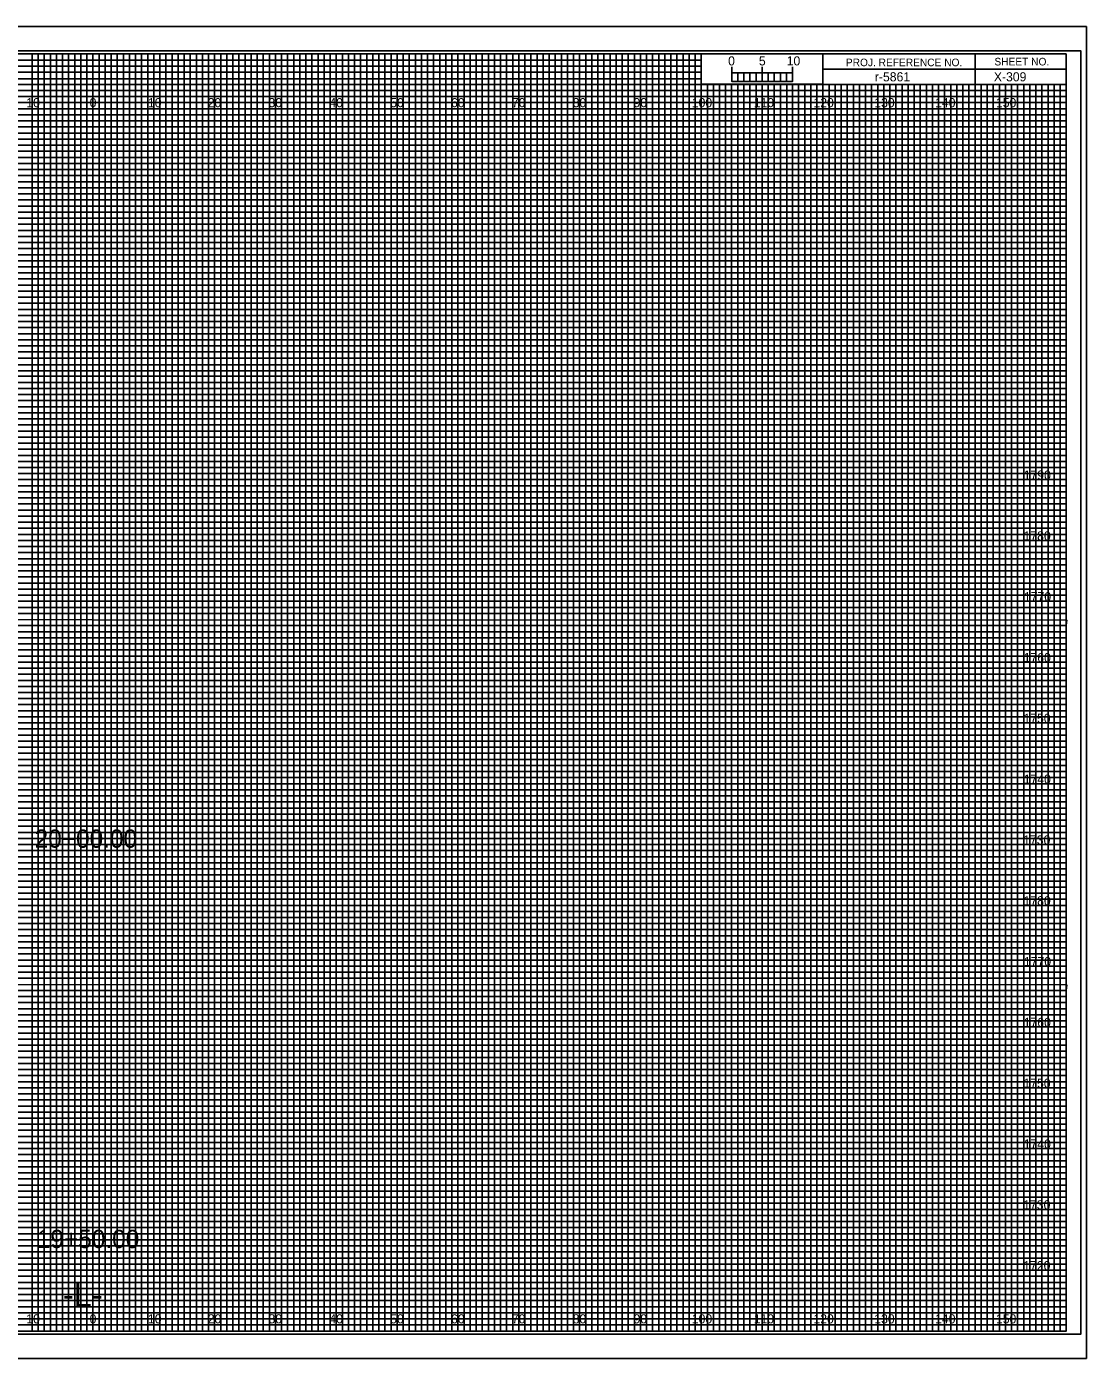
# Model space of a CAD drawing. Extents: x -15 to 323, y -5 to 6170.
# Drawn here: x 149.1 to 323.3, y 1095.5 to 1314.5 of the extents above; entities that cross this region are included whole.
import ezdxf

# ---------------------------------------------------------------- set-up
doc = ezdxf.new("R2010")
doc.units = 0
for name, color, linetype in [('Prop XS Alignment Label', 7, 'Continuous'), ('Prop XS Bar Scale Labels', 7, 'Continuous'), ('Prop XS DDE', 7, 'Continuous'), ('Prop XS DDE Earthwork Shape', 7, 'Continuous'), ('Prop XS DDE Slope Text', 7, 'Continuous'), ('Prop XS DDE Text', 7, 'Continuous'), ('Prop XS Earthwork Shape', 7, 'Continuous'), ('Prop XS Noise Wall', 7, 'Continuous'), ('Prop XS Project Number', 7, 'Continuous'), ('Prop XS Retaining Wall', 7, 'Continuous'), ('Prop XS Station Labels', 7, 'Continuous'), ('Prop XS Temporary Shoring', 7, 'Continuous'), ('Scratch_Level_3', 7, 'Continuous'), ('Scratch_Level_7', 7, 'Continuous'), ('Scratch_Level_8', 7, 'Continuous'), ('Sheet Cross Section Grid Minor 1 CELL', 7, 'Continuous')]:
    doc.layers.add(name, color=color, linetype=linetype)

msp = doc.modelspace()

# ---------------------------------------------------------------- linework, layer by layer
at = {"layer": 'Prop XS Alignment Label'}
for p, q in [((265, 1305.49), (265, 1307.9)), ((265, 1306.9), (265, 1307.9)), ((270, 1305.49), (270, 1307.9)), ((275, 1305.49), (275, 1307.9)), ((275, 1306.9), (275, 1307.9))]:
    msp.add_line(p, q, dxfattribs=at)
for points in [[(275, 1306.9), (265, 1306.9), (265, 1305.49), (275, 1305.49)], [(265, 1306.9), (266, 1306.9), (266, 1305.49), (265, 1305.49)], [(267, 1306.9), (268, 1306.9), (268, 1305.49), (267, 1305.49)], [(269, 1306.9), (270, 1306.9), (270, 1305.49), (269, 1305.49)], [(271, 1306.9), (272, 1306.9), (272, 1305.49), (271, 1305.49)], [(273, 1306.9), (274, 1306.9), (274, 1305.49), (273, 1305.49)]]:
    msp.add_lwpolyline(points, close=True, dxfattribs=at)
at = {"layer": 'Prop XS DDE'}
msp.add_lwpolyline([(-13.4, 1095.5), (323.3, 1095.5), (323.3, 1314.5), (-13.4, 1314.5)], close=True, dxfattribs=at)
at = {"layer": 'Prop XS DDE Slope Text'}
msp.add_lwpolyline([(-10.8, 1099.5), (322.4, 1099.5), (322.4, 1310.5), (-10.8, 1310.5)], close=True, dxfattribs=at)
at = {"layer": 'Prop XS DDE Text'}
for p, q in [((150, 1100), (150, 1310)), ((160, 1100), (160, 1310)), ((170, 1100), (170, 1310)), ((180, 1100), (180, 1310)), ((190, 1100), (190, 1310)), ((200, 1100), (200, 1310)), ((210, 1100), (210, 1310)), ((220, 1100), (220, 1310)), ((230, 1100), (230, 1310)), ((240, 1100), (240, 1310)), ((250, 1100), (250, 1310)), ((260, 1100), (260, 1304.69)), ((270, 1100), (270, 1304.69)), ((280, 1100), (280, 1304.69)), ((290, 1100), (290, 1304.69)), ((300, 1100), (300, 1304.69)), ((310, 1100), (310, 1304.69)), ((0, 1300), (320, 1300)), ((0, 1290), (320, 1290)), ((0, 1280), (320, 1280)), ((0, 1270), (320, 1270)), ((0, 1260), (320, 1260)), ((0, 1250), (320, 1250)), ((0, 1240), (320, 1240)), ((0, 1230), (320, 1230)), ((0, 1220), (320, 1220)), ((0, 1210), (320, 1210)), ((0, 1200), (320, 1200)), ((0, 1190), (320, 1190)), ((0, 1180), (320, 1180)), ((0, 1170), (320, 1170)), ((0, 1160), (320, 1160)), ((0, 1150), (320, 1150)), ((0, 1140), (320, 1140)), ((0, 1130), (320, 1130)), ((0, 1120), (320, 1120)), ((0, 1110), (320, 1110))]:
    msp.add_line(p, q, dxfattribs=at)
at = {"layer": 'Prop XS Earthwork Shape'}
for p, q in [((150, 1310), (140, 1310)), ((150, 1100), (150, 1310)), ((170, 1310), (160, 1310)), ((160, 1310), (160, 1100)), ((170, 1100), (170, 1310)), ((190, 1310), (180, 1310)), ((180, 1310), (180, 1100)), ((190, 1100), (190, 1310)), ((210, 1310), (200, 1310)), ((200, 1310), (200, 1100)), ((210, 1100), (210, 1310)), ((230, 1310), (220, 1310)), ((220, 1310), (220, 1100)), ((230, 1100), (230, 1310)), ((250, 1310), (240, 1310)), ((240, 1310), (240, 1100)), ((250, 1100), (250, 1310)), ((260, 1310), (260, 1100)), ((270, 1100), (270, 1305)), ((290, 1305), (280, 1305)), ((280, 1305), (280, 1100)), ((290, 1100), (290, 1305)), ((310, 1305), (300, 1305)), ((300, 1305), (300, 1100)), ((310, 1100), (310, 1305)), ((160, 1100), (150, 1100)), ((180, 1100), (170, 1100)), ((200, 1100), (190, 1100)), ((220, 1100), (210, 1100)), ((240, 1100), (230, 1100)), ((260, 1100), (250, 1100)), ((280, 1100), (270, 1100)), ((300, 1100), (290, 1100)), ((320, 1100), (310, 1100)), ((320, 1100), (320, 1100))]:
    msp.add_line(p, q, dxfattribs=at)
for points in [[(0, 1300), (320, 1300), (320, 1290), (0, 1290)], [(0, 1280), (320, 1280), (320, 1270), (0, 1270)], [(0, 1260), (320, 1260), (320, 1250), (0, 1250)], [(0, 1240), (320, 1240), (320, 1230), (0, 1230)], [(0, 1220), (320, 1220), (320, 1210), (0, 1210)], [(0, 1200), (320, 1200), (320, 1190), (0, 1190)], [(0, 1180), (320, 1180), (320, 1170), (0, 1170)], [(0, 1160), (320, 1160), (320, 1150), (0, 1150)], [(0, 1140), (320, 1140), (320, 1130), (0, 1130)], [(0, 1120), (320, 1120), (320, 1110), (0, 1110)]]:
    msp.add_lwpolyline(points, dxfattribs=at)
at = {"layer": 'Prop XS Noise Wall'}
for p, q in [((305, 1310), (305, 1305)), ((305, 1305), (305, 1310)), ((280, 1307.5), (280, 1305)), ((320, 1307.49), (280, 1307.49)), ((280, 1305), (320, 1305))]:
    msp.add_line(p, q, dxfattribs=at)
for points in [[(320, 1310), (0, 1310), (0, 1100), (320, 1100)], [(280, 1310), (260, 1310), (260, 1305.03), (280, 1305.03)], [(320, 1310), (280, 1310), (280, 1305), (320, 1305)]]:
    msp.add_lwpolyline(points, close=True, dxfattribs=at)
at = {"layer": 'Prop XS Retaining Wall'}
for p, q in [((267, 1305), (266.01, 1305)), ((266.01, 1305), (266.01, 1100)), ((267, 1100), (267, 1305)), ((269, 1305), (268, 1305)), ((268, 1305), (268, 1100)), ((269, 1100), (269, 1305)), ((266.01, 1100), (265, 1100)), ((268, 1100), (267, 1100))]:
    msp.add_line(p, q, dxfattribs=at)
for points in [[(150, 1100), (151, 1100), (151, 1310), (152, 1310), (152, 1100)], [(152, 1100), (153, 1100), (153, 1310), (154, 1310), (154, 1100)], [(155, 1100), (156, 1100), (156, 1310), (157, 1310), (157, 1100)], [(157, 1100), (158, 1100), (158, 1310), (159, 1310), (159, 1100)], [(160, 1100), (161, 1100), (161, 1310), (162, 1310), (162, 1100)], [(162, 1100), (163, 1100), (163, 1310), (164, 1310), (164, 1100)], [(165, 1100), (166, 1100), (166, 1310), (167, 1310), (167, 1100)], [(167, 1100), (168, 1100), (168, 1310), (169, 1310), (169, 1100)], [(170, 1100), (171, 1100), (171, 1310), (172, 1310), (172, 1100)], [(172, 1100), (173, 1100), (173, 1310), (174, 1310), (174, 1100)], [(175, 1100), (176, 1100), (176, 1310), (177, 1310), (177, 1100)], [(177, 1100), (178, 1100), (178, 1310), (179, 1310), (179, 1100)], [(180, 1100), (181, 1100), (181, 1310), (182, 1310), (182, 1100)], [(182, 1100), (183, 1100), (183, 1310), (184, 1310), (184, 1100)], [(185, 1100), (186, 1100), (186, 1310), (187, 1310), (187, 1100)], [(187, 1100), (188, 1100), (188, 1310), (189, 1310), (189, 1100)], [(190, 1100), (191, 1100), (191, 1310), (192, 1310), (192, 1100)], [(192, 1100), (193, 1100), (193, 1310), (194, 1310), (194, 1100)], [(195, 1100), (196, 1100), (196, 1310), (197, 1310), (197, 1100)], [(197, 1100), (198, 1100), (198, 1310), (199, 1310), (199, 1100)], [(200, 1100), (201, 1100), (201, 1310), (202, 1310), (202, 1100)], [(202, 1100), (203, 1100), (203, 1310), (204, 1310), (204, 1100)], [(205, 1100), (206, 1100), (206, 1310), (207, 1310), (207, 1100)], [(207, 1100), (208, 1100), (208, 1310), (209, 1310), (209, 1100)], [(210, 1100), (211, 1100), (211, 1310), (212, 1310), (212, 1100)], [(212, 1100), (213, 1100), (213, 1310), (214, 1310), (214, 1100)], [(215, 1100), (216, 1100), (216, 1310), (217, 1310), (217, 1100)], [(217, 1100), (218, 1100), (218, 1310), (219, 1310), (219, 1100)], [(220, 1100), (221, 1100), (221, 1310), (222, 1310), (222, 1100)], [(222, 1100), (223, 1100), (223, 1310), (224, 1310), (224, 1100)], [(225, 1100), (226, 1100), (226, 1310), (227, 1310), (227, 1100)], [(227, 1100), (228, 1100), (228, 1310), (229, 1310), (229, 1100)], [(230, 1100), (231, 1100), (231, 1310), (232, 1310), (232, 1100)], [(232, 1100), (233, 1100), (233, 1310), (234, 1310), (234, 1100)], [(235, 1100), (236, 1100), (236, 1310), (237, 1310), (237, 1100)], [(237, 1100), (238, 1100), (238, 1310), (239, 1310), (239, 1100)], [(240, 1100), (241, 1100), (241, 1310), (242, 1310), (242, 1100)], [(242, 1100), (243, 1100), (243, 1310), (244, 1310), (244, 1100)], [(245, 1100), (246, 1100), (246, 1310), (247, 1310), (247, 1100)], [(247, 1100), (248, 1100), (248, 1310), (249, 1310), (249, 1100)], [(250, 1100), (251, 1100), (251, 1310), (252, 1310), (252, 1100)], [(252, 1100), (253, 1100), (253, 1310), (254, 1310), (254, 1100)], [(255, 1100), (256, 1100), (256, 1310), (257, 1310), (257, 1100)], [(257, 1100), (258, 1100), (258, 1310), (259, 1310), (259, 1100)], [(260, 1100), (261, 1100), (261, 1305), (262.02, 1305), (262.02, 1100)], [(262, 1100), (263, 1100), (263, 1305), (263.99, 1305), (263.99, 1100)], [(270, 1100), (270.98, 1100), (270.98, 1305), (272, 1305), (272, 1100)], [(272, 1100), (273, 1100), (273, 1305), (274.05, 1305), (274.05, 1100)], [(275, 1100), (276, 1100), (276, 1305), (277, 1305), (277, 1100)], [(277, 1100), (278, 1100), (278, 1305), (279, 1305), (279, 1100)], [(280, 1100), (281, 1100), (281, 1305), (282, 1305), (282, 1100)], [(282, 1100), (283, 1100), (283, 1305), (284, 1305), (284, 1100)], [(285, 1100), (286, 1100), (286, 1305), (287, 1305), (287, 1100)], [(287, 1100), (288, 1100), (288, 1305), (289, 1305), (289, 1100)], [(290, 1100), (291, 1100), (291, 1305), (292, 1305), (292, 1100)], [(292, 1100), (293, 1100), (293, 1305), (294, 1305), (294, 1100)], [(295, 1100), (296, 1100), (296, 1305), (297, 1305), (297, 1100)], [(297, 1100), (298, 1100), (298, 1305), (299, 1305), (299, 1100)], [(300, 1100), (301, 1100), (301, 1305), (302, 1305), (302, 1100)], [(302, 1100), (303, 1100), (303, 1305), (304, 1305), (304, 1100)], [(305, 1100), (306, 1100), (306, 1305), (307, 1305), (307, 1100)], [(307, 1100), (308, 1100), (308, 1305), (309, 1305), (309, 1100)], [(310, 1100), (311, 1100), (311, 1305), (312, 1305), (312, 1100)], [(312, 1100), (313, 1100), (313, 1305), (314, 1305), (314, 1100)], [(315, 1100), (316, 1100), (316, 1305), (317, 1305), (317, 1100)], [(317, 1100), (318, 1100), (318, 1305), (319, 1305), (319, 1100)]]:
    msp.add_lwpolyline(points, dxfattribs=at)
at = {"layer": 'Prop XS Station Labels'}
for points in [[(145, 1100), (155, 1100), (155, 1310), (165, 1310), (165, 1100), (175, 1100), (175, 1310), (185, 1310), (185, 1100), (195, 1100), (195, 1310), (205, 1310), (205, 1100), (215, 1100), (215, 1310), (225, 1310), (225, 1100), (235, 1100), (235, 1310), (245, 1310), (245, 1100), (255, 1100), (255, 1310), (259.93, 1310), (260, 1310), (260, 1305), (264.99, 1305), (264.99, 1100), (275, 1100), (275, 1305), (285, 1305), (285, 1100), (295, 1100), (295, 1305), (305, 1305), (305, 1100), (315, 1100), (315, 1305)], [(0, 1305), (275, 1305)], [(0, 1285), (320, 1285), (320, 1295), (0, 1295)], [(0, 1265), (320, 1265), (320, 1275), (0, 1275)], [(0, 1245), (320, 1245), (320, 1255), (0, 1255)], [(0, 1225), (320, 1225), (320, 1235), (0, 1235)], [(0, 1205), (320, 1205), (320, 1215), (0, 1215)], [(0, 1185), (320, 1185), (320, 1195), (0, 1195)], [(0, 1165), (320, 1165), (320, 1175), (0, 1175)], [(0, 1145), (320, 1145), (320, 1155), (0, 1155)], [(0, 1125), (320, 1125), (320, 1135), (0, 1135)], [(0, 1105), (320, 1105), (320, 1115), (0, 1115)]]:
    msp.add_lwpolyline(points, dxfattribs=at)
at = {"layer": 'Scratch_Level_7'}
for p, q in [((323.3, 1314.5), (-13.4, 1314.5)), ((-13.4, 1095.5), (323.3, 1095.5))]:
    msp.add_line(p, q, dxfattribs=at)
at = {"layer": 'Sheet Cross Section Grid Minor 1 CELL'}
for p, q in [((0, 1309), (260, 1309)), ((260, 1307.98), (0, 1307.98)), ((260, 1309), (260, 1307.98)), ((0, 1307), (260, 1307)), ((260, 1305.89), (0, 1305.89)), ((260, 1307), (260, 1305.89)), ((0, 1304), (320, 1304))]:
    msp.add_line(p, q, dxfattribs=at)
for points in [[(0, 1303), (270, 1303), (320, 1303), (320, 1302), (0, 1302)], [(0, 1301), (320, 1301), (320, 1299), (0, 1299)], [(0, 1298), (320, 1298), (320, 1297), (0, 1296.98)], [(0, 1296), (320, 1296), (320, 1294), (0, 1294)], [(0, 1293), (320, 1293), (320, 1292), (0, 1292)], [(0, 1291), (320, 1291), (320, 1289), (0, 1289)], [(0, 1288), (320, 1288), (320, 1287), (0, 1287)], [(0, 1286), (320, 1286), (320, 1284), (0, 1284)], [(0, 1283), (320, 1283), (320, 1282), (0, 1282)], [(0, 1281), (320, 1281), (320, 1279), (0, 1279)], [(0, 1278), (320, 1278), (320, 1277), (0, 1277)], [(0, 1276), (320, 1276), (320, 1273.95), (320, 1273), (320, 1272), (0, 1272)], [(0, 1274), (320, 1274), (320, 1273), (0, 1273)], [(0, 1271), (320, 1271), (320, 1269), (0, 1269.03)], [(0, 1269.03), (320, 1269), (320, 1268), (0, 1268)], [(0, 1267), (320, 1267), (320, 1266), (0, 1266)], [(0, 1264), (320, 1264), (320, 1263), (0, 1263)], [(0, 1262), (320, 1262), (320, 1261), (0, 1261)], [(-0.07, 1258.89), (320, 1258.89), (320, 1257.88), (-0.07, 1257.88)], [(0, 1257), (320, 1257), (320, 1256), (0, 1256)], [(0, 1254), (320, 1254), (320, 1253), (0, 1253)], [(0, 1252), (320, 1252), (320, 1251), (0, 1251)], [(0, 1249), (320, 1249), (320, 1248), (0, 1248)], [(0, 1247), (320, 1247), (320, 1246), (0, 1246)], [(0, 1244), (320, 1244), (320, 1243), (0, 1243)], [(0, 1242), (320, 1242), (320, 1241), (0, 1241)], [(0, 1239), (320, 1239), (319.99, 1237.98), (0, 1238)], [(0, 1237), (320, 1237), (320, 1236), (0, 1236)], [(0, 1234), (320, 1234), (320, 1233), (0, 1233)], [(0, 1232), (320, 1232), (320, 1231), (0, 1231)], [(0, 1229), (320, 1229), (320, 1228), (0, 1228)], [(0, 1227), (320, 1227), (320, 1226), (0, 1226)], [(0, 1224), (320, 1224), (320, 1223), (0, 1223)], [(0, 1222), (320, 1222), (320, 1221), (0, 1221)], [(0, 1219), (320, 1219), (320, 1218), (0, 1218)], [(0, 1216.99), (320.07, 1216.91), (320, 1216), (0, 1216)], [(0, 1214), (320, 1214), (320, 1213), (0, 1213)], [(0, 1212), (320, 1212), (320, 1211), (0, 1211)], [(0, 1209), (320, 1209), (320, 1208), (0, 1208)], [(0, 1207), (320, 1207), (320, 1206), (0, 1206)], [(0, 1204), (320, 1204), (320, 1203), (0, 1203)], [(0, 1202), (320, 1202), (320, 1201), (0, 1201)], [(0, 1199), (320, 1199), (320, 1198), (0, 1198)], [(0, 1197), (320, 1197), (320, 1196), (0, 1196)], [(0, 1194), (320, 1194), (320, 1193), (0, 1193)], [(0, 1192), (320, 1192), (320, 1191), (0, 1191)], [(0, 1189), (320, 1189), (320, 1188), (0, 1188)], [(0, 1187), (320, 1187), (320, 1186), (0, 1186)], [(0, 1184), (320, 1184), (320, 1183), (0, 1183)], [(0, 1182), (320, 1182), (320, 1181), (0, 1181)], [(0, 1179), (320, 1179), (319.99, 1177.98), (0, 1178)], [(0, 1177), (320, 1177), (320, 1176), (0, 1176)], [(0, 1174), (320, 1174), (320, 1173), (0, 1173)], [(0, 1172), (320, 1172), (320, 1171), (0, 1171)], [(0, 1169), (320, 1169), (320, 1168), (0, 1168)], [(0, 1167), (320, 1167), (320, 1166), (0, 1166)], [(0, 1164), (320, 1164), (320, 1163), (0, 1163)], [(0, 1162), (320, 1162), (320, 1161), (0, 1161)], [(0, 1159), (320, 1159), (320, 1158), (0, 1158)], [(0, 1156.99), (320.07, 1156.91), (320, 1156), (0, 1156)], [(0, 1154), (320, 1154), (320, 1153), (0, 1153)], [(0, 1152), (320, 1152), (320, 1151), (0, 1151)], [(0, 1149), (320, 1149), (320, 1148), (0, 1148)], [(0, 1147), (320, 1147), (320, 1146), (0, 1146)], [(0, 1144), (320, 1144), (320, 1143), (0, 1143)], [(0, 1142), (320, 1142), (320, 1141), (0, 1141)], [(0, 1139), (320, 1139), (320, 1138), (0, 1138)], [(0, 1137), (320, 1137), (320, 1136), (0, 1136)], [(0, 1134), (320, 1134), (320, 1133), (0, 1133)], [(0, 1132), (320, 1132), (320, 1131), (0, 1131)], [(0, 1129), (320, 1129), (320, 1128), (0, 1128)], [(0, 1127), (320, 1127), (320, 1126), (0, 1126)], [(0, 1124), (320, 1124), (320, 1123), (0, 1123)], [(0, 1122), (320, 1122), (320, 1121), (0, 1121)], [(0, 1119), (320, 1119), (320, 1118), (0, 1118)], [(0, 1117), (320, 1117), (320, 1116), (0, 1116)], [(0, 1114), (320, 1114), (320, 1113), (0, 1113)], [(0, 1112), (320, 1112), (320, 1111), (0, 1111)], [(0, 1109), (320, 1109), (320, 1108), (0, 1108)], [(0, 1107), (320, 1107), (320, 1106), (0, 1106)], [(0, 1104), (320, 1104), (320, 1103), (0, 1103)], [(0, 1102), (320, 1102), (320, 1101), (0, 1101)]]:
    msp.add_lwpolyline(points, dxfattribs=at)

# ---------------------------------------------------------------- texts
at = {"layer": 'Prop XS Alignment Label'}
for s, height, p in [('0', 1.5, (264.41, 1308.12)), ('-L-', 4, (155.06, 1104))]:
    msp.add_text(s, height=height, dxfattribs=at).set_placement(p)
at = {"layer": 'Prop XS Bar Scale Labels'}
for s, p in [('5', (269.47, 1308.12)), ('10', (274.04, 1308.12))]:
    msp.add_text(s, height=1.5, dxfattribs=at).set_placement(p)
at = {"layer": 'Prop XS DDE Earthwork Shape'}
msp.add_text('X-309', height=1.5, dxfattribs=at).set_placement((308.09, 1305.5))
at = {"layer": 'Prop XS Noise Wall'}
for s, p in [('PROJ. REFERENCE NO.', (283.77, 1307.99)), ('SHEET NO.', (308.19, 1308.12))]:
    msp.add_text(s, height=1.25, dxfattribs=at).set_placement(p)
at = {"layer": 'Prop XS Project Number'}
msp.add_text('r-5861', height=1.5, dxfattribs=at).set_placement((288.53, 1305.5))
at = {"layer": 'Prop XS Temporary Shoring'}
for s, p in [('20+00.00', (150.41, 1179.47)), ('19+50.00', (150.77, 1113.64))]:
    msp.add_text(s, height=3, dxfattribs=at).set_placement(p)
at = {"layer": 'Scratch_Level_3'}
for s, p in [('1790', (313, 1240)), ('1780', (312.98, 1230)), ('1770', (313.04, 1220)), ('1760', (313, 1210)), ('1750', (312.96, 1200)), ('1740', (313, 1190)), ('1730', (312.92, 1180)), ('1780', (312.98, 1170)), ('1770', (313.04, 1160)), ('1760', (313, 1150)), ('1750', (312.96, 1140)), ('1740', (313, 1130)), ('1730', (312.92, 1120)), ('1720', (312.93, 1110))]:
    msp.add_text(s, height=1.5, dxfattribs=at).set_placement(p)
at = {"layer": 'Scratch_Level_8'}
for s, p in [('10', (149.04, 1301.25)), ('0', (159.45, 1301.25)), ('0', (159.45, 1301.25)), ('10', (169.04, 1301.25)), ('20', (178.86, 1301.25)), ('30', (188.86, 1301.25)), ('40', (198.86, 1301.25)), ('50', (208.86, 1301.25)), ('60', (218.86, 1301.25)), ('70', (228.86, 1301.25)), ('80', (238.86, 1301.25)), ('90', (248.86, 1301.25)), ('100', (258.44, 1301.25)), ('110', (268.62, 1301.25)), ('120', (278.44, 1301.25)), ('130', (288.44, 1301.25)), ('140', (298.44, 1301.25)), ('150', (308.44, 1301.25)), ('10', (149.04, 1101.25)), ('0', (159.45, 1101.25)), ('0', (159.45, 1101.25)), ('10', (169.04, 1101.25)), ('20', (178.86, 1101.25)), ('30', (188.86, 1101.25)), ('40', (198.86, 1101.25)), ('50', (208.86, 1101.25)), ('60', (218.86, 1101.25)), ('70', (228.86, 1101.25)), ('80', (238.86, 1101.25)), ('90', (248.86, 1101.25)), ('100', (258.44, 1101.25)), ('110', (268.62, 1101.25)), ('120', (278.44, 1101.25)), ('130', (288.44, 1101.25)), ('140', (298.44, 1101.25)), ('150', (308.44, 1101.25))]:
    msp.add_text(s, height=1.5, dxfattribs=at).set_placement(p)

doc.saveas('drawing.dxf')
